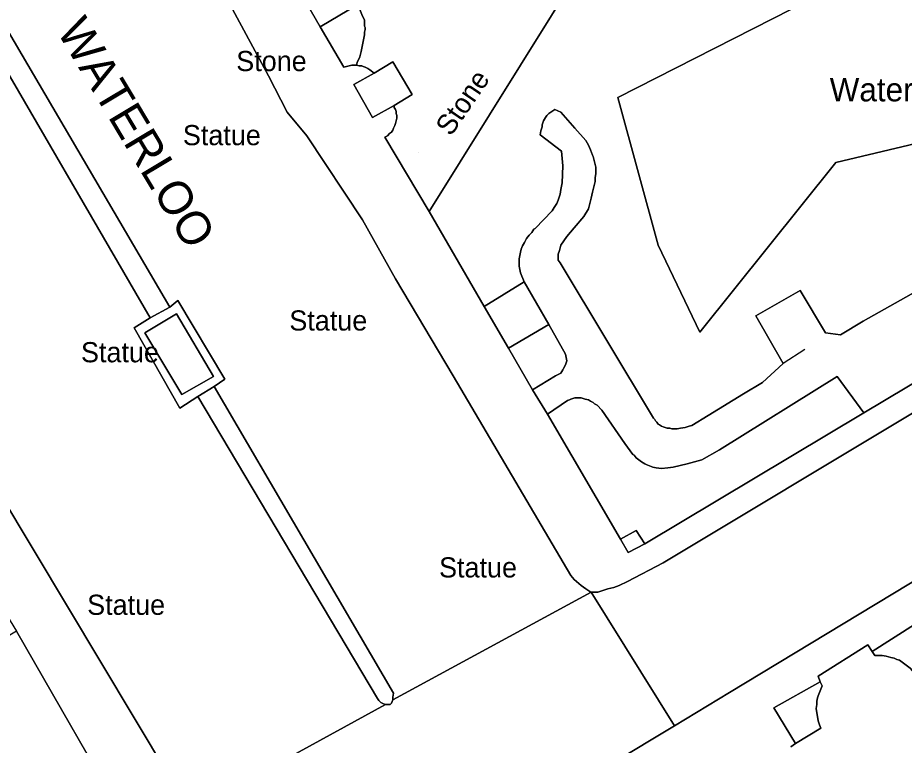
# Model space of a CAD drawing. Extents: x 529240 to 530363, y 179600 to 180767.
# Drawn here: x 529719 to 529784.9, y 180266.5 to 180320.6 of the extents above; entities that cross this region are included whole.
import ezdxf

# ---------------------------------------------------------------- set-up
doc = ezdxf.new("R2010")
doc.units = 0
for name, color, linetype in [('Building', 7, 'Continuous'), ('General surface', 7, 'Continuous'), ('Natural environment', 7, 'Continuous'), ('Path', 7, 'Continuous'), ('Road Or Track', 7, 'Continuous'), ('Roadside', 7, 'Continuous'), ('Structure', 7, 'Continuous'), ('Unclassified', 7, 'Continuous')]:
    doc.layers.add(name, color=color, linetype=linetype)

msp = doc.modelspace()

# ---------------------------------------------------------------- linework, layer by layer
at = {"layer": 'Building'}
for points in [[(529785.4, 180272.2), (529784.6, 180272.8), (529784.4, 180272.85), (529784.2, 180272.95), (529783.95, 180273), (529783.6, 180273.1), (529783.3, 180273.15), (529782.75, 180273.15), (529782.55, 180273.45), (529782.25, 180273.95), (529778.55, 180271.6), (529778.7, 180271.2), (529778.85, 180270.9), (529778.55, 180270.15), (529778.5, 180270), (529778.45, 180269.75), (529778.45, 180269.5), (529778.4, 180269.2), (529778.55, 180268.3), (529778.65, 180268), (529778.75, 180267.75), (529776.85, 180266.6), (529776.5, 180266.35)], [(529782.55, 180273.45), (529782.25, 180273.95), (529778.55, 180271.6), (529778.7, 180271.2)], [(529787.15, 180273), (529785.55, 180272), (529785.4, 180272.2), (529784.6, 180272.8), (529784.4, 180272.85), (529784.2, 180272.95), (529783.95, 180273), (529783.6, 180273.1), (529783.3, 180273.15), (529782.75, 180273.15), (529782.55, 180273.45)], [(529778.7, 180271.2), (529778.85, 180270.9), (529778.55, 180270.15), (529778.5, 180270), (529778.45, 180269.75), (529778.45, 180269.5), (529778.4, 180269.2), (529778.55, 180268.3), (529778.65, 180268), (529778.75, 180267.75), (529776.85, 180266.6)], [(529776.85, 180266.6), (529776.5, 180266.35)]]:
    msp.add_lwpolyline(points, dxfattribs=at)
at = {"layer": 'General surface'}
for points in [[(529780.5, 180336.25), (529786.65, 180326.35), (529763.65, 180314.65), (529766.65, 180303.65), (529769.75, 180297.2), (529779.85, 180309.8), (529803.05, 180315.3), (529788.1, 180340.25), (529789.25, 180340.9), (529788.95, 180341.35), (529790.55, 180342.3), (529787.5, 180347), (529772.7, 180338.15)], [(529744.3, 180321.55), (529741.5, 180319.9), (529743.25, 180316.9), (529743.85, 180317.05), (529744.2, 180317.05), (529744.25, 180317.25), (529744.45, 180317.65), (529744.55, 180318.05), (529744.8, 180319.3), (529744.8, 180319.5), (529744.85, 180319.7), (529744.85, 180319.85), (529744.8, 180319.95), (529744.8, 180320.4), (529744.6, 180320.8)], [(529757.3, 180292.9), (529759, 180293.95), (529759.4, 180294.15), (529759.55, 180294.4), (529759.6, 180294.5), (529759.75, 180294.75), (529759.85, 180295.05), (529759.75, 180295.55), (529758.5, 180297.75), (529755.5, 180296)], [(529785.7, 180275.45), (529782.55, 180273.45), (529782.75, 180273.15), (529783.3, 180273.15), (529783.6, 180273.1), (529783.95, 180273), (529784.2, 180272.95), (529784.4, 180272.85), (529784.6, 180272.8), (529785.4, 180272.2), (529785.55, 180272), (529787.15, 180273)], [(529776.85, 180266.6), (529778.75, 180267.75), (529778.65, 180268), (529778.55, 180268.3), (529778.4, 180269.2), (529778.45, 180269.5), (529778.45, 180269.75), (529778.5, 180270), (529778.55, 180270.15), (529778.85, 180270.9), (529778.7, 180271.2), (529775.25, 180269.25)]]:
    msp.add_lwpolyline(points, close=True, dxfattribs=at)
for points in [[(529733.15, 180334.4), (529741.5, 180319.9), (529744.3, 180321.55)], [(529744.6, 180320.8), (529744.8, 180320.4), (529744.8, 180319.95), (529744.85, 180319.85), (529744.85, 180319.7), (529744.8, 180319.5), (529744.8, 180319.3), (529744.55, 180318.05), (529744.45, 180317.65), (529744.25, 180317.25), (529744.2, 180317.05), (529744.4, 180317), (529744.6, 180317), (529744.7, 180316.95), (529744.85, 180316.9), (529745.05, 180316.8), (529745.2, 180316.7), (529745.5, 180316.45), (529746.9, 180317.3), (529748.35, 180314.85), (529747, 180314.05), (529747, 180313.9), (529747.1, 180313.75), (529747.15, 180313.6), (529747.15, 180313.45), (529747.2, 180313.3), (529747.2, 180313.1), (529747.1, 180312.7), (529747.05, 180312.55), (529746.95, 180312.35), (529746.9, 180312.2), (529746.8, 180312.05), (529746.65, 180311.95), (529746.5, 180311.8), (529746.3, 180311.7), (529749.6, 180306.15), (529765.5, 180331.65)], [(529765.5, 180331.65), (529749.6, 180306.15)], [(529786.65, 180326.35), (529763.65, 180314.65), (529766.65, 180303.65), (529769.75, 180297.2), (529779.85, 180309.8), (529803.05, 180315.3)]]:
    msp.add_lwpolyline(points, dxfattribs=at)
at = {"layer": 'Natural environment'}
for points in [[(529765.5, 180331.65), (529749.6, 180306.15), (529753.7, 180299.1), (529756.67, 180300.93), (529756.4, 180301.6), (529756.3, 180302.1), (529756.3, 180302.65), (529756.4, 180303.15), (529756.45, 180303.35), (529756.55, 180303.6), (529756.7, 180303.85), (529756.85, 180304.15), (529757.05, 180304.4), (529757.25, 180304.6), (529757.4, 180304.85), (529757.5, 180304.9), (529758.75, 180306.2), (529758.9, 180306.45), (529759.1, 180306.75), (529759.2, 180307), (529759.35, 180307.45), (529759.4, 180307.8), (529759.5, 180308.3), (529759.55, 180309.55), (529759.45, 180310.65), (529757.85, 180311.85), (529757.9, 180312.15), (529758, 180312.45), (529758, 180312.6), (529758.1, 180312.9), (529758.25, 180313.15), (529758.35, 180313.3), (529758.5, 180313.45), (529758.95, 180313.75), (529759.4, 180313.55), (529760.45, 180312.35), (529761.25, 180311.45), (529761.45, 180311.1), (529761.6, 180310.75), (529761.75, 180310.35), (529761.8, 180310.25), (529762, 180309.45), (529762, 180308.95), (529761.95, 180308.7), (529761.95, 180308.4), (529761.75, 180307.6), (529761.65, 180307.15), (529761.45, 180306.35), (529761.1, 180305.8), (529760.4, 180304.95), (529759.85, 180304.3), (529759.4, 180303.65), (529759.3, 180303.25), (529759.2, 180303), (529759.2, 180302.55), (529759.35, 180302.35), (529766.3, 180290.8), (529766.4, 180290.7), (529766.45, 180290.6), (529766.55, 180290.5), (529766.65, 180290.35), (529766.75, 180290.3), (529766.9, 180290.2), (529767, 180290.15), (529767.3, 180290.05), (529767.5, 180290.05), (529767.65, 180290), (529768.05, 180290), (529768.3, 180290.05), (529768.65, 180290.1), (529768.95, 180290.2), (529769.15, 180290.25), (529770.35, 180291), (529773, 180292.6), (529774.4, 180293.45), (529775.95, 180294.85), (529773.9, 180298.4), (529777.2, 180300.3), (529779.1, 180297.15), (529780.2, 180297), (529781.9, 180298), (529785.85, 180300.25)], [(529803.05, 180315.3), (529779.85, 180309.8), (529769.75, 180297.2), (529766.65, 180303.65), (529763.65, 180314.65), (529786.65, 180326.35)]]:
    msp.add_lwpolyline(points, dxfattribs=at)
for points in [[(529765.65, 180281.45), (529781.95, 180291.2), (529779.95, 180293.9), (529771.2, 180288.45), (529769.9, 180287.7), (529768.8, 180287.4), (529767.75, 180287.15), (529767.35, 180287.1), (529766.9, 180287.05), (529766.5, 180287.1), (529766.25, 180287.15), (529765.75, 180287.35), (529765.65, 180287.4), (529765.4, 180287.55), (529765, 180287.85), (529764.85, 180288.05), (529764.75, 180288.1), (529764.15, 180288.9), (529762.45, 180291.4), (529762.1, 180291.75), (529761.9, 180291.85), (529761.8, 180291.95), (529761.6, 180292.05), (529761.45, 180292.15), (529761.2, 180292.2), (529760.9, 180292.3), (529760.45, 180292.3), (529760.15, 180292.2), (529760.05, 180292.15), (529759.9, 180292.1), (529758.4, 180291.1), (529763.85, 180281.8), (529765, 180282.45)], [(529716, 180255.214), (529717.9, 180252.6), (529726.9, 180258.05), (529726.2, 180259.2), (529727.5, 180260), (529718.9, 180274.95), (529717.2, 180273.95), (529716, 180275.918)]]:
    msp.add_lwpolyline(points, close=True, dxfattribs=at)
at = {"layer": 'Path'}
msp.add_lwpolyline([(529785.85, 180300.25), (529781.9, 180298), (529780.2, 180297), (529779.1, 180297.15), (529777.2, 180300.3), (529773.9, 180298.4), (529775.95, 180294.85), (529774.4, 180293.45), (529773, 180292.6), (529770.35, 180291), (529769.15, 180290.25), (529768.95, 180290.2), (529768.65, 180290.1), (529768.3, 180290.05), (529768.05, 180290), (529767.65, 180290), (529767.5, 180290.05), (529767.3, 180290.05), (529767, 180290.15), (529766.9, 180290.2), (529766.75, 180290.3), (529766.65, 180290.35), (529766.55, 180290.5), (529766.45, 180290.6), (529766.4, 180290.7), (529766.3, 180290.8), (529759.35, 180302.35), (529759.2, 180302.55), (529759.2, 180303), (529759.3, 180303.25), (529759.4, 180303.65), (529759.85, 180304.3), (529760.4, 180304.95), (529761.1, 180305.8), (529761.45, 180306.35), (529761.65, 180307.15), (529761.75, 180307.6), (529761.95, 180308.4), (529761.95, 180308.7), (529762, 180308.95), (529762, 180309.45), (529761.8, 180310.25), (529761.75, 180310.35), (529761.6, 180310.75), (529761.45, 180311.1), (529761.25, 180311.45), (529760.45, 180312.35), (529759.4, 180313.55), (529758.95, 180313.75), (529758.5, 180313.45), (529758.35, 180313.3), (529758.25, 180313.15), (529758.1, 180312.9), (529758, 180312.6), (529758, 180312.45), (529757.9, 180312.15), (529757.85, 180311.85), (529759.45, 180310.65), (529759.55, 180309.55), (529759.5, 180308.3), (529759.4, 180307.8), (529759.35, 180307.45), (529759.2, 180307), (529759.1, 180306.75), (529758.9, 180306.45), (529758.75, 180306.2), (529757.5, 180304.9), (529757.4, 180304.85), (529757.25, 180304.6), (529757.05, 180304.4), (529756.85, 180304.15), (529756.7, 180303.85), (529756.55, 180303.6), (529756.45, 180303.35), (529756.4, 180303.15), (529756.3, 180302.65), (529756.3, 180302.1), (529756.4, 180301.6), (529756.67, 180300.93), (529758.5, 180297.75), (529759.75, 180295.55), (529759.85, 180295.05), (529759.75, 180294.75), (529759.6, 180294.5), (529759.55, 180294.4), (529759.4, 180294.15), (529759, 180293.95), (529757.3, 180292.9), (529758.4, 180291.1), (529759.9, 180292.1), (529760.05, 180292.15), (529760.15, 180292.2), (529760.45, 180292.3), (529760.9, 180292.3), (529761.2, 180292.2), (529761.45, 180292.15), (529761.6, 180292.05), (529761.8, 180291.95), (529761.9, 180291.85), (529762.1, 180291.75), (529762.45, 180291.4), (529764.15, 180288.9), (529764.75, 180288.1), (529764.85, 180288.05), (529765, 180287.85), (529765.4, 180287.55), (529765.65, 180287.4), (529765.75, 180287.35), (529766.25, 180287.15), (529766.5, 180287.1), (529766.9, 180287.05), (529767.35, 180287.1), (529767.75, 180287.15), (529768.8, 180287.4), (529769.9, 180287.7), (529771.2, 180288.45), (529779.95, 180293.9), (529781.95, 180291.2), (529786.8, 180294.1)], dxfattribs=at)
at = {"layer": 'Road Or Track'}
for points in [[(529720.6, 180346.95), (529720.75, 180346.5), (529720.9, 180346.15), (529721.3, 180345.45), (529721.4, 180345.3), (529731.15, 180328.45), (529734.15, 180322.75), (529737.65, 180316.25), (529739.05, 180313.55), (529740.5, 180311.8), (529744.65, 180305.55), (529747.1, 180301.15), (529751.4, 180293.95), (529760.15, 180279.1), (529760.4, 180278.8), (529760.75, 180278.5), (529760.9, 180278.35), (529761.25, 180278.1), (529761.55, 180277.9), (529761.65, 180277.85)], [(529716, 180323.446), (529730.3, 180299.05), (529730.9, 180299.55), (529734.4, 180293.7), (529733.6, 180293.15), (529746.95, 180270.35), (529746.9, 180270.05), (529746.9, 180269.85), (529761.65, 180277.85), (529761.55, 180277.9), (529761.25, 180278.1), (529760.9, 180278.35), (529760.75, 180278.5), (529760.4, 180278.8), (529760.15, 180279.1), (529751.4, 180293.95), (529747.1, 180301.15), (529744.65, 180305.55), (529740.5, 180311.8), (529739.05, 180313.55), (529737.65, 180316.25), (529734.15, 180322.75)], [(529730.3, 180299.05), (529716, 180323.446)], [(529716, 180320.312), (529728.85, 180298.25)], [(529822.05, 180313.05), (529767, 180280.05), (529764.35, 180278.65), (529763.75, 180278.35), (529763.35, 180278.2), (529762.9, 180278.1), (529762.15, 180277.85), (529761.65, 180277.85), (529767.85, 180267.93), (529771.95, 180270.4), (529793.75, 180283.55)], [(529761.65, 180277.85), (529762.15, 180277.85), (529762.9, 180278.1), (529763.35, 180278.2), (529763.75, 180278.35), (529764.35, 180278.65), (529767, 180280.05), (529822.05, 180313.05)], [(529730.3, 180299.05), (529730.9, 180299.55), (529734.4, 180293.7)], [(529732.4, 180292.4), (529731.05, 180291.55), (529727.65, 180297.5), (529728.85, 180298.25)], [(529734.4, 180293.7), (529733.6, 180293.15)], [(529733.6, 180293.15), (529746.95, 180270.35), (529746.9, 180270.05), (529746.9, 180269.85)], [(529746.35, 180269.5), (529746.2, 180269.55), (529746, 180269.65), (529745.85, 180269.8), (529745.75, 180269.95), (529732.4, 180292.4)], [(529716, 180288.42), (529716.45, 180287.5), (529717.65, 180285.2), (529730.2, 180264.25), (529730.4, 180263.95), (529730.55, 180263.65), (529730.75, 180263.35), (529730.85, 180263.05), (529731, 180262.7), (529731.05, 180262.35), (529731.1, 180262.25), (529731.15, 180261.85), (529731.2, 180261.5), (529731.2, 180261.2)], [(529798.15, 180282.7), (529798, 180282.9), (529797.85, 180283.15), (529797.65, 180283.35), (529797.4, 180283.5), (529797.2, 180283.7), (529796.9, 180283.85), (529796.7, 180284), (529796.4, 180284.1), (529795.9, 180284.2), (529794.95, 180284.2), (529794.75, 180284.15), (529794.15, 180283.85), (529793.75, 180283.55), (529771.95, 180270.4), (529767.85, 180267.93)], [(529758.4, 180262.25), (529767.85, 180267.93), (529761.65, 180277.85), (529746.9, 180269.85), (529746.8, 180269.6), (529746.7, 180269.5), (529746.35, 180269.5), (529731.2, 180261.2)], [(529746.9, 180269.85), (529746.8, 180269.6), (529746.7, 180269.5), (529746.35, 180269.5)], [(529767.85, 180267.93), (529758.4, 180262.25), (529753.52, 180259.26), (529752.14, 180258.41), (529746.1, 180254.7), (529741.25, 180251.95), (529741.05, 180251.8), (529740.6, 180251.35), (529740.5, 180251.15), (529740.35, 180251), (529740.25, 180250.75), (529740.15, 180250.35), (529740.15, 180249.85), (529740.3, 180249.25), (529740.65, 180248.65), (529742.25, 180245.75)]]:
    msp.add_lwpolyline(points, dxfattribs=at)
msp.add_lwpolyline([(529716, 180288.42), (529716.45, 180287.5), (529717.65, 180285.2), (529730.2, 180264.25), (529730.4, 180263.95), (529730.55, 180263.65), (529730.75, 180263.35), (529730.85, 180263.05), (529731, 180262.7), (529731.05, 180262.35), (529731.1, 180262.25), (529731.15, 180261.85), (529731.2, 180261.5), (529731.2, 180261.2), (529746.35, 180269.5), (529746.2, 180269.55), (529746, 180269.65), (529745.85, 180269.8), (529745.75, 180269.95), (529732.4, 180292.4), (529731.05, 180291.55), (529727.65, 180297.5), (529728.85, 180298.25), (529716, 180320.312)], close=True, dxfattribs=at)
at = {"layer": 'Roadside'}
for points in [[(529786.8, 180294.1), (529781.95, 180291.2), (529765.65, 180281.45), (529764.4, 180280.8), (529763.85, 180281.8), (529758.4, 180291.1), (529757.3, 180292.9), (529755.5, 180296), (529753.7, 180299.1), (529749.6, 180306.15), (529746.3, 180311.7), (529746.5, 180311.8), (529746.65, 180311.95), (529746.8, 180312.05), (529746.9, 180312.2), (529746.95, 180312.35), (529747.05, 180312.55), (529747.1, 180312.7), (529747.2, 180313.1), (529747.2, 180313.3), (529747.15, 180313.45), (529747.15, 180313.6), (529747.1, 180313.75), (529747, 180313.9), (529747, 180314.05), (529745.4, 180313.15), (529744, 180315.6), (529745.5, 180316.45), (529745.2, 180316.7), (529745.05, 180316.8), (529744.85, 180316.9), (529744.7, 180316.95), (529744.6, 180317), (529744.4, 180317), (529744.2, 180317.05), (529743.85, 180317.05), (529743.25, 180316.9), (529741.5, 180319.9), (529733.15, 180334.4)], [(529734.15, 180322.75), (529737.65, 180316.25), (529739.05, 180313.55), (529740.5, 180311.8), (529744.65, 180305.55), (529747.1, 180301.15), (529751.4, 180293.95), (529760.15, 180279.1), (529760.4, 180278.8), (529760.75, 180278.5), (529760.9, 180278.35), (529761.25, 180278.1), (529761.55, 180277.9), (529761.65, 180277.85), (529762.15, 180277.85), (529762.9, 180278.1), (529763.35, 180278.2), (529763.75, 180278.35), (529764.35, 180278.65), (529767, 180280.05), (529822.05, 180313.05)], [(529730.2, 180264.25), (529717.65, 180285.2), (529716.45, 180287.5), (529716, 180288.42), (529716, 180279.844), (529716.5, 180279), (529717.7, 180276.95), (529718.9, 180274.95), (529727.5, 180260)], [(529793.75, 180283.55), (529771.95, 180270.4), (529767.85, 180267.93), (529758.4, 180262.25)], [(529776.5, 180266.35), (529776.85, 180266.6), (529775.25, 180269.25), (529778.7, 180271.2), (529778.55, 180271.6), (529782.25, 180273.95), (529782.55, 180273.45), (529785.7, 180275.45)]]:
    msp.add_lwpolyline(points, dxfattribs=at)
for points in [[(529716, 180320.312), (529728.85, 180298.25), (529730.3, 180299.05), (529716, 180323.446)], [(529730.3, 180299.05), (529728.85, 180298.25), (529727.65, 180297.5), (529731.05, 180291.55), (529732.4, 180292.4), (529733.6, 180293.15), (529734.4, 180293.7), (529730.9, 180299.55)], [(529728.45, 180297.15), (529730.8, 180298.55), (529733.55, 180293.9), (529731.2, 180292.55)], [(529746.9, 180269.85), (529746.9, 180270.05), (529746.95, 180270.35), (529733.6, 180293.15), (529732.4, 180292.4), (529745.75, 180269.95), (529745.85, 180269.8), (529746, 180269.65), (529746.2, 180269.55), (529746.35, 180269.5), (529746.7, 180269.5), (529746.8, 180269.6)]]:
    msp.add_lwpolyline(points, close=True, dxfattribs=at)
at = {"layer": 'Structure'}
for p, q in [((529738, 180317.05), (529738, 180317.05)), ((529748.8, 180310.55), (529748.8, 180310.55))]:
    msp.add_line(p, q, dxfattribs=at)
for points in [[(529747, 180314.05), (529748.35, 180314.85), (529746.9, 180317.3), (529745.5, 180316.45), (529744, 180315.6), (529745.4, 180313.15)], [(529753.7, 180299.1), (529755.5, 180296), (529758.5, 180297.75), (529756.67, 180300.93)], [(529728.45, 180297.15), (529731.2, 180292.55), (529733.55, 180293.9), (529730.8, 180298.55)], [(529765.65, 180281.45), (529765, 180282.45), (529763.85, 180281.8), (529764.4, 180280.8)]]:
    msp.add_lwpolyline(points, close=True, dxfattribs=at)
at = {"layer": 'Unclassified'}
for points in [[(529733.15, 180334.4), (529741.5, 180319.9)], [(529741.5, 180319.9), (529744.3, 180321.55)], [(529744.3, 180321.55), (529744.6, 180320.8), (529744.8, 180320.4), (529744.8, 180319.95), (529744.85, 180319.85), (529744.85, 180319.7), (529744.8, 180319.5), (529744.8, 180319.3), (529744.55, 180318.05), (529744.45, 180317.65), (529744.25, 180317.25), (529744.2, 180317.05)], [(529741.5, 180319.9), (529743.25, 180316.9)], [(529745.5, 180316.45), (529746.9, 180317.3), (529748.35, 180314.85), (529747, 180314.05)], [(529743.25, 180316.9), (529743.85, 180317.05), (529744.2, 180317.05)], [(529744.2, 180317.05), (529744.4, 180317), (529744.6, 180317), (529744.7, 180316.95), (529744.85, 180316.9), (529745.05, 180316.8), (529745.2, 180316.7), (529745.5, 180316.45)], [(529744, 180315.6), (529745.5, 180316.45)], [(529744, 180315.6), (529745.4, 180313.15)], [(529747, 180314.05), (529745.4, 180313.15)], [(529746.3, 180311.7), (529746.5, 180311.8), (529746.65, 180311.95), (529746.8, 180312.05), (529746.9, 180312.2), (529746.95, 180312.35), (529747.05, 180312.55), (529747.1, 180312.7), (529747.2, 180313.1), (529747.2, 180313.3), (529747.15, 180313.45), (529747.15, 180313.6), (529747.1, 180313.75), (529747, 180313.9), (529747, 180314.05)], [(529756.67, 180300.93), (529756.4, 180301.6), (529756.3, 180302.1), (529756.3, 180302.65), (529756.4, 180303.15), (529756.45, 180303.35), (529756.55, 180303.6), (529756.7, 180303.85), (529756.85, 180304.15), (529757.05, 180304.4), (529757.25, 180304.6), (529757.4, 180304.85), (529757.5, 180304.9), (529758.75, 180306.2), (529758.9, 180306.45), (529759.1, 180306.75), (529759.2, 180307), (529759.35, 180307.45), (529759.4, 180307.8), (529759.5, 180308.3), (529759.55, 180309.55), (529759.45, 180310.65), (529757.85, 180311.85), (529757.9, 180312.15), (529758, 180312.45), (529758, 180312.6), (529758.1, 180312.9), (529758.25, 180313.15), (529758.35, 180313.3), (529758.5, 180313.45), (529758.95, 180313.75)], [(529758.95, 180313.75), (529759.4, 180313.55), (529760.45, 180312.35), (529761.25, 180311.45), (529761.45, 180311.1), (529761.6, 180310.75), (529761.75, 180310.35), (529761.8, 180310.25), (529762, 180309.45), (529762, 180308.95), (529761.95, 180308.7), (529761.95, 180308.4), (529761.75, 180307.6), (529761.65, 180307.15), (529761.45, 180306.35), (529761.1, 180305.8), (529760.4, 180304.95), (529759.85, 180304.3), (529759.4, 180303.65), (529759.3, 180303.25), (529759.2, 180303), (529759.2, 180302.55), (529759.35, 180302.35), (529766.3, 180290.8), (529766.4, 180290.7), (529766.45, 180290.6), (529766.55, 180290.5), (529766.65, 180290.35), (529766.75, 180290.3), (529766.9, 180290.2), (529767, 180290.15), (529767.3, 180290.05), (529767.5, 180290.05), (529767.65, 180290), (529768.05, 180290), (529768.3, 180290.05), (529768.65, 180290.1), (529768.95, 180290.2), (529769.15, 180290.25), (529770.35, 180291), (529773, 180292.6), (529774.4, 180293.45), (529775.95, 180294.85)], [(529779.1, 180297.15), (529780.2, 180297), (529781.9, 180298), (529785.85, 180300.25), (529790.75, 180303.3), (529793.8, 180305.25), (529796.7, 180307.25), (529798.9, 180308.7), (529801.05, 180310.15), (529801.15, 180310.25), (529801.35, 180310.35), (529801.5, 180310.45), (529801.6, 180310.6), (529801.8, 180310.8), (529801.9, 180311), (529801.95, 180311.15), (529802.05, 180311.35), (529802.05, 180311.5), (529802.1, 180311.7), (529802.1, 180312.15), (529801.9, 180312.95), (529801.75, 180313.3)], [(529746.3, 180311.7), (529749.6, 180306.15)], [(529749.6, 180306.15), (529753.7, 180299.1)], [(529753.7, 180299.1), (529756.67, 180300.93)], [(529756.67, 180300.93), (529758.5, 180297.75)], [(529775.95, 180294.85), (529773.9, 180298.4), (529777.2, 180300.3), (529779.1, 180297.15)], [(529728.85, 180298.25), (529730.3, 180299.05)], [(529753.7, 180299.1), (529755.5, 180296)], [(529728.45, 180297.15), (529730.8, 180298.55), (529733.55, 180293.9), (529731.2, 180292.55), (529728.45, 180297.15)], [(529758.5, 180297.75), (529755.5, 180296)], [(529758.5, 180297.75), (529759.75, 180295.55), (529759.85, 180295.05), (529759.75, 180294.75), (529759.6, 180294.5), (529759.55, 180294.4), (529759.4, 180294.15), (529759, 180293.95), (529757.3, 180292.9)], [(529755.5, 180296), (529757.3, 180292.9)], [(529777.55, 180295.9), (529775.95, 180294.85)], [(529781.95, 180291.2), (529779.95, 180293.9), (529771.2, 180288.45), (529769.9, 180287.7), (529768.8, 180287.4), (529767.75, 180287.15), (529767.35, 180287.1), (529766.9, 180287.05), (529766.5, 180287.1), (529766.25, 180287.15), (529765.75, 180287.35), (529765.65, 180287.4), (529765.4, 180287.55), (529765, 180287.85), (529764.85, 180288.05), (529764.75, 180288.1), (529764.15, 180288.9), (529762.45, 180291.4), (529762.1, 180291.75), (529761.9, 180291.85), (529761.8, 180291.95), (529761.6, 180292.05), (529761.45, 180292.15), (529761.2, 180292.2), (529760.9, 180292.3), (529760.45, 180292.3), (529760.15, 180292.2), (529760.05, 180292.15), (529759.9, 180292.1), (529758.4, 180291.1)], [(529781.95, 180291.2), (529786.8, 180294.1)], [(529733.6, 180293.15), (529732.4, 180292.4)], [(529757.3, 180292.9), (529758.4, 180291.1)], [(529758.4, 180291.1), (529763.85, 180281.8)], [(529765.65, 180281.45), (529781.95, 180291.2)], [(529763.85, 180281.8), (529765, 180282.45), (529765.65, 180281.45)], [(529763.85, 180281.8), (529764.4, 180280.8), (529765.65, 180281.45)], [(529746.9, 180269.85), (529761.65, 180277.85)], [(529761.65, 180277.85), (529767.85, 180267.93)], [(529785.7, 180275.45), (529782.55, 180273.45)], [(529727.5, 180260), (529718.9, 180274.95)], [(529778.7, 180271.2), (529775.25, 180269.25), (529776.85, 180266.6)], [(529746.35, 180269.5), (529731.2, 180261.2)]]:
    msp.add_lwpolyline(points, dxfattribs=at)

# ---------------------------------------------------------------- texts
at = {"layer": 'General surface'}
msp.add_text('Waterloo Gardens', height=1.75, dxfattribs=at).set_placement((529779.4, 180314.35))
at = {"layer": 'Road Or Track'}
msp.add_text('WATERLOO', height=2.5, rotation=300.9, dxfattribs=at).set_placement((529721.85, 180319.6))
at = {"layer": 'Structure'}
for s, p in [('Stone', (529735.25, 180316.6)), ('Statue', (529731.28, 180311.09)), ('Statue', (529739.2, 180297.31)), ('Statue', (529723.7, 180294.95)), ('Statue', (529750.34, 180278.95)), ('Statue', (529724.16, 180276.17))]:
    msp.add_text(s, height=1.5, dxfattribs=at).set_placement(p)
msp.add_text('Stone', height=1.5, rotation=55.7, dxfattribs=at).set_placement((529751.22, 180311.69))

doc.saveas('drawing.dxf')
